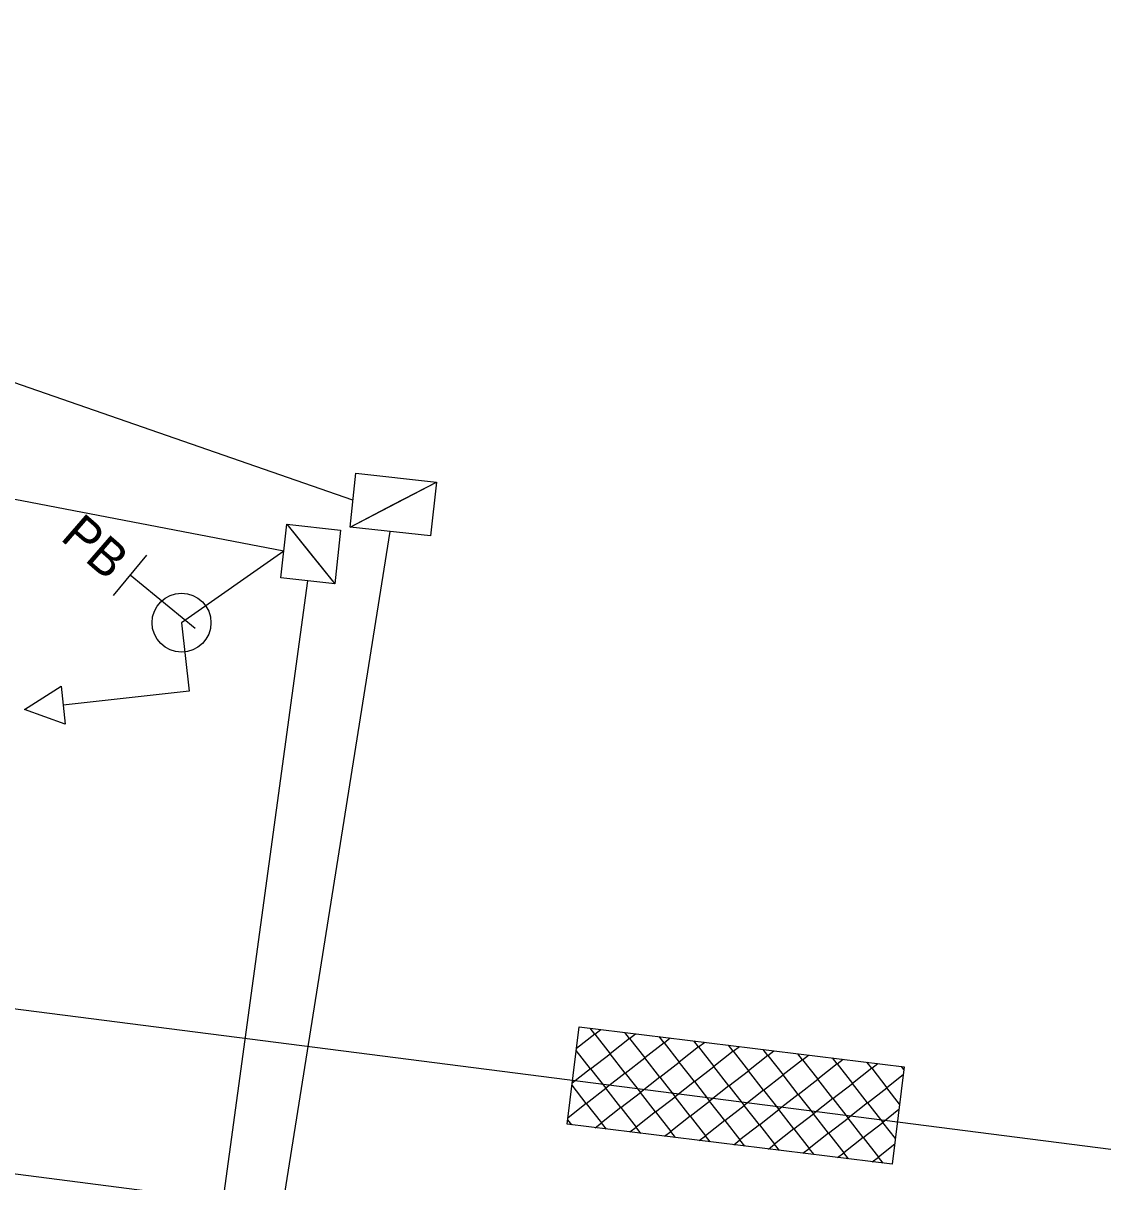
# Model space of a CAD drawing. Extents: x -200 to 1730068, y -325 to 756043.
# Drawn here: x 1725453.3 to 1725519.8, y 658633.1 to 658703.8 of the extents above; entities that cross this region are included whole.
import ezdxf

# ---------------------------------------------------------------- set-up
doc = ezdxf.new("R2010")
doc.units = 0
for name, color, linetype in [('DESIGN - SCRATCH - User 3', 7, 'Continuous'), ('DESIGN - TRAFFIC CONTROL PERMANENT - Signal Poles', 7, 'Continuous'), ('DESIGN - TRAFFIC CONTROL PERMANENT - Signalization', 7, 'Continuous')]:
    doc.layers.add(name, color=color, linetype=linetype)

msp = doc.modelspace()

# ---------------------------------------------------------------- linework, layer by layer
at = {"layer": 'DESIGN - SCRATCH - User 3'}
for p, q in [((1725398.421, 658650.577), (1725519.755, 658635.059)), ((1725397.153, 658640.658), (1725518.487, 658625.14))]:
    msp.add_line(p, q, dxfattribs=at)
at = {"layer": 'DESIGN - TRAFFIC CONTROL PERMANENT - Signal Poles'}
msp.add_line((1725462.995, 658667.202), (1725462.995, 658667.202), dxfattribs=at)
msp.add_circle((1725462.995, 658667.202), 1.8, dxfattribs=at)
msp.add_circle((1725462.995, 658667.202), 1.8, dxfattribs=at)
at = {"layer": 'DESIGN - TRAFFIC CONTROL PERMANENT - Signalization'}
for p, q in [((1725473.465, 658674.685), (1725389.548, 658703.817)), ((1725469.25, 658671.577), (1725419.489, 658681.103)), ((1725473.288, 658673.044), (1725478.563, 658675.794)), ((1725469.43, 658673.217), (1725472.351, 658669.577)), ((1725458.454, 658564.235), (1725475.748, 658672.779)), ((1725458.842, 658668.866), (1725460.868, 658671.336)), ((1725469.25, 658671.577), (1725462.995, 658667.202)), ((1725470.89, 658671.397), (1725470.89, 658671.397)), ((1725457.063, 658569.934), (1725470.711, 658669.757)), ((1725463.822, 658666.848), (1725459.855, 658670.101)), ((1725462.995, 658667.202), (1725463.457, 658663.014)), ((1725488.239, 658642.073), (1725487.121, 658641.193)), ((1725488.239, 658642.073), (1725487.95, 658642.443)), ((1725488.239, 658642.073), (1725488.612, 658642.362)), ((1725488.239, 658642.073), (1725489.17, 658640.881)), ((1725490.353, 658641.813), (1725490.064, 658642.183)), ((1725490.353, 658641.813), (1725490.726, 658642.102)), ((1725492.467, 658641.553), (1725492.178, 658641.923)), ((1725490.353, 658641.813), (1725489.17, 658640.881)), ((1725490.353, 658641.813), (1725491.284, 658640.62)), ((1725492.467, 658641.553), (1725491.284, 658640.62)), ((1725492.467, 658641.553), (1725492.84, 658641.841)), ((1725492.467, 658641.553), (1725493.398, 658640.36)), ((1725494.581, 658641.292), (1725493.398, 658640.36)), ((1725494.581, 658641.292), (1725494.292, 658641.662)), ((1725494.581, 658641.292), (1725494.954, 658641.581)), ((1725494.581, 658641.292), (1725495.512, 658640.1)), ((1725496.695, 658641.032), (1725496.406, 658641.402)), ((1725496.695, 658641.032), (1725497.068, 658641.321)), ((1725487.978, 658639.959), (1725487.107, 658641.075)), ((1725487.978, 658639.959), (1725489.17, 658640.881)), ((1725490.092, 658639.699), (1725489.17, 658640.881)), ((1725490.092, 658639.699), (1725491.284, 658640.62)), ((1725492.206, 658639.439), (1725491.284, 658640.62)), ((1725496.695, 658641.032), (1725495.512, 658640.1)), ((1725496.695, 658641.032), (1725497.626, 658639.839)), ((1725498.809, 658640.772), (1725497.626, 658639.839)), ((1725498.809, 658640.772), (1725498.52, 658641.142)), ((1725498.809, 658640.772), (1725499.182, 658641.06)), ((1725498.809, 658640.772), (1725499.74, 658639.579)), ((1725500.923, 658640.511), (1725499.74, 658639.579)), ((1725500.923, 658640.511), (1725500.634, 658640.881)), ((1725500.923, 658640.511), (1725501.296, 658640.8)), ((1725500.923, 658640.511), (1725501.854, 658639.319)), ((1725503.037, 658640.251), (1725502.748, 658640.621)), ((1725503.037, 658640.251), (1725503.41, 658640.54)), ((1725487.978, 658639.959), (1725486.861, 658639.079)), ((1725487.978, 658639.959), (1725488.909, 658638.767)), ((1725492.206, 658639.439), (1725493.398, 658640.36)), ((1725494.32, 658639.178), (1725493.398, 658640.36)), ((1725494.32, 658639.178), (1725495.512, 658640.1)), ((1725496.434, 658638.918), (1725495.512, 658640.1)), ((1725496.434, 658638.918), (1725497.626, 658639.839)), ((1725498.548, 658638.658), (1725497.626, 658639.839)), ((1725503.037, 658640.251), (1725501.854, 658639.319)), ((1725503.037, 658640.251), (1725503.968, 658639.058)), ((1725505.151, 658639.991), (1725503.968, 658639.058)), ((1725505.151, 658639.991), (1725504.862, 658640.361)), ((1725505.151, 658639.991), (1725505.524, 658640.279)), ((1725505.151, 658639.991), (1725506.082, 658638.798)), ((1725507.116, 658639.921), (1725506.976, 658640.1)), ((1725490.092, 658639.699), (1725488.909, 658638.767)), ((1725490.092, 658639.699), (1725491.023, 658638.506)), ((1725492.206, 658639.439), (1725491.023, 658638.506)), ((1725492.206, 658639.439), (1725493.137, 658638.246)), ((1725494.32, 658639.178), (1725493.137, 658638.246)), ((1725494.32, 658639.178), (1725495.252, 658637.986)), ((1725498.548, 658638.658), (1725499.74, 658639.579)), ((1725500.662, 658638.397), (1725499.74, 658639.579)), ((1725500.662, 658638.397), (1725501.854, 658639.319)), ((1725502.776, 658638.137), (1725501.854, 658639.319)), ((1725507.074, 658639.58), (1725506.082, 658638.798)), ((1725487.718, 658637.845), (1725486.847, 658638.961)), ((1725487.718, 658637.845), (1725488.909, 658638.767)), ((1725489.832, 658637.585), (1725488.909, 658638.767)), ((1725489.832, 658637.585), (1725491.023, 658638.506)), ((1725491.946, 658637.325), (1725491.023, 658638.506)), ((1725496.434, 658638.918), (1725495.252, 658637.986)), ((1725496.434, 658638.918), (1725497.366, 658637.725)), ((1725498.548, 658638.658), (1725497.366, 658637.725)), ((1725498.548, 658638.658), (1725499.48, 658637.465)), ((1725500.662, 658638.397), (1725499.48, 658637.465)), ((1725500.662, 658638.397), (1725501.594, 658637.205)), ((1725502.776, 658638.137), (1725503.968, 658639.058)), ((1725504.89, 658637.877), (1725503.968, 658639.058)), ((1725504.89, 658637.877), (1725506.082, 658638.798)), ((1725506.856, 658637.807), (1725506.082, 658638.798)), ((1725487.718, 658637.845), (1725486.601, 658636.965)), ((1725487.718, 658637.845), (1725488.649, 658636.653)), ((1725491.946, 658637.325), (1725493.137, 658638.246)), ((1725494.06, 658637.064), (1725493.137, 658638.246)), ((1725494.06, 658637.064), (1725495.252, 658637.986)), ((1725496.174, 658636.804), (1725495.252, 658637.986)), ((1725496.174, 658636.804), (1725497.366, 658637.725)), ((1725498.288, 658636.544), (1725497.366, 658637.725)), ((1725502.776, 658638.137), (1725501.594, 658637.205)), ((1725502.776, 658638.137), (1725503.708, 658636.944)), ((1725504.89, 658637.877), (1725503.708, 658636.944)), ((1725504.89, 658637.877), (1725505.822, 658636.684)), ((1725489.832, 658637.585), (1725488.649, 658636.653)), ((1725489.832, 658637.585), (1725490.763, 658636.392)), ((1725491.946, 658637.325), (1725490.763, 658636.392)), ((1725491.946, 658637.325), (1725492.877, 658636.132)), ((1725494.06, 658637.064), (1725492.877, 658636.132)), ((1725494.06, 658637.064), (1725494.991, 658635.872)), ((1725498.288, 658636.544), (1725499.48, 658637.465)), ((1725500.402, 658636.283), (1725499.48, 658637.465)), ((1725500.402, 658636.283), (1725501.594, 658637.205)), ((1725502.516, 658636.023), (1725501.594, 658637.205)), ((1725506.814, 658637.466), (1725505.822, 658636.684)), ((1725486.829, 658636.536), (1725486.586, 658636.847)), ((1725488.269, 658636.359), (1725488.649, 658636.653)), ((1725488.943, 658636.276), (1725488.649, 658636.653)), ((1725490.383, 658636.098), (1725490.763, 658636.392)), ((1725491.057, 658636.015), (1725490.763, 658636.392)), ((1725496.174, 658636.804), (1725494.991, 658635.872)), ((1725496.174, 658636.804), (1725497.105, 658635.611)), ((1725498.288, 658636.544), (1725497.105, 658635.611)), ((1725498.288, 658636.544), (1725499.219, 658635.351)), ((1725500.402, 658636.283), (1725499.219, 658635.351)), ((1725500.402, 658636.283), (1725501.333, 658635.091)), ((1725502.516, 658636.023), (1725503.708, 658636.944)), ((1725504.63, 658635.763), (1725503.708, 658636.944)), ((1725504.63, 658635.763), (1725505.822, 658636.684)), ((1725506.595, 658635.693), (1725505.822, 658636.684)), ((1725492.497, 658635.838), (1725492.877, 658636.132)), ((1725493.171, 658635.755), (1725492.877, 658636.132)), ((1725494.611, 658635.578), (1725494.991, 658635.872)), ((1725495.285, 658635.495), (1725494.991, 658635.872)), ((1725496.725, 658635.317), (1725497.105, 658635.611)), ((1725497.399, 658635.234), (1725497.105, 658635.611)), ((1725502.516, 658636.023), (1725501.333, 658635.091)), ((1725502.516, 658636.023), (1725503.447, 658634.83)), ((1725504.63, 658635.763), (1725503.447, 658634.83)), ((1725504.63, 658635.763), (1725505.561, 658634.57)), ((1725498.839, 658635.057), (1725499.219, 658635.351)), ((1725499.513, 658634.974), (1725499.219, 658635.351)), ((1725500.953, 658634.797), (1725501.333, 658635.091)), ((1725501.628, 658634.714), (1725501.333, 658635.091)), ((1725506.553, 658635.352), (1725505.561, 658634.57)), ((1725503.067, 658634.536), (1725503.447, 658634.83)), ((1725503.742, 658634.453), (1725503.447, 658634.83)), ((1725505.181, 658634.276), (1725505.561, 658634.57)), ((1725505.856, 658634.193), (1725505.561, 658634.57)), ((1725506.402, 658634.126), (1725506.402, 658634.126))]:
    msp.add_line(p, q, dxfattribs=at)
for points in [[(1725473.288, 658673.044), (1725473.642, 658676.325), (1725478.563, 658675.794), (1725478.209, 658672.513)], [(1725478.209, 658672.513), (1725473.288, 658673.044), (1725475.926, 658674.419), (1725478.563, 658675.794)], [(1725469.43, 658673.217), (1725472.71, 658672.858), (1725472.351, 658669.577), (1725469.07, 658669.937)], [(1725469.07, 658669.937), (1725469.43, 658673.217), (1725470.89, 658671.397), (1725472.351, 658669.577)], [(1725455.636, 658663.332), (1725455.891, 658661.006), (1725453.408, 658661.91)], [(1725487.285, 658642.525), (1725507.136, 658640.081), (1725506.402, 658634.126), (1725486.552, 658636.57)]]:
    msp.add_lwpolyline(points, close=True, dxfattribs=at)
msp.add_lwpolyline([(1725463.457, 658663.014), (1725455.764, 658662.169), (1725455.891, 658661.006), (1725453.408, 658661.91), (1725455.636, 658663.332), (1725455.764, 658662.169)], dxfattribs=at)

# ---------------------------------------------------------------- texts
msp.add_text('PB', height=2.2147, rotation=319.05617, dxfattribs=at).set_placement((1725455.528, 658672.311))

doc.saveas('drawing.dxf')
